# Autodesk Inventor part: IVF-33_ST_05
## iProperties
Created: 2008-10
Part Number: IVF-33_ST_05
Material: 3.3206  AlMgSi 0.5  H22
Document SubType Name: Blech
Designer: Gawin
Density: 2.66 g/cm^3
Mass: 67.4968 g
Surface Area: 257.894 cm^2
Volume: 25.3747 cm^3
Stock Number: IVF-33_ST_05
Author: Gawin
